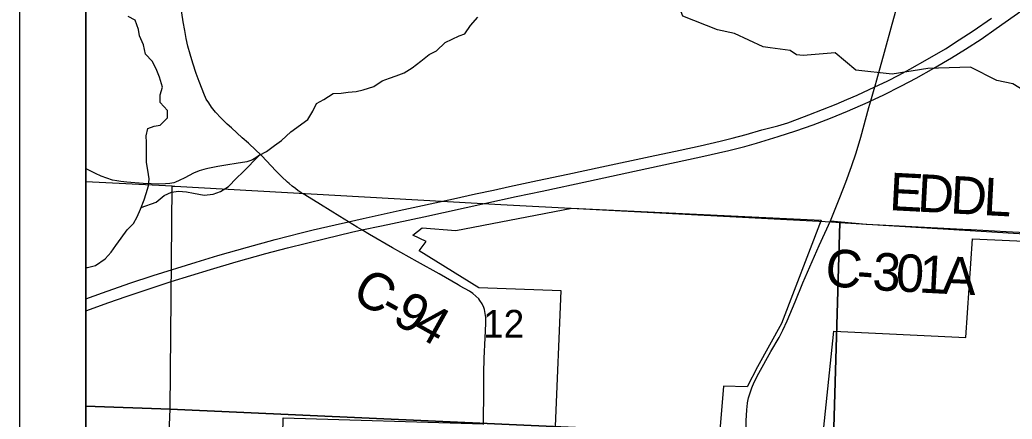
# Model space of a CAD drawing. Extents: x 0 to 34, y 0 to 22.
# Drawn here: x 23.917 to 25.417, y 15.184 to 15.788 of the extents above; entities that cross this region are included whole.
import ezdxf

# ---------------------------------------------------------------- set-up
doc = ezdxf.new("R2010")
doc.units = 0
for name, color, linetype in [('GM_X_Adjacent_County', 7, 'Continuous'), ('GM_X_Corporation', 7, 'Continuous'), ('GM_X_County', 7, 'Continuous'), ('GM_X_County_Road', 7, 'Continuous'), ('GM_X_County_Road_Text', 7, 'Continuous'), ('GM_X_Minor_River', 7, 'Continuous'), ('GM_X_Section', 7, 'Continuous'), ('GM_X_Section_Text', 7, 'Continuous'), ('GM_X_State_Route', 7, 'Continuous'), ('GM_X_Township', 7, 'Continuous'), ('GM_X_Township_Road', 7, 'Continuous'), ('SH_Data', 7, 'Continuous')]:
    doc.layers.add(name, color=color, linetype=linetype)

msp = doc.modelspace()

# ---------------------------------------------------------------- linework, layer by layer
at = {"layer": 'GM_X_Adjacent_County'}
msp.add_lwpolyline([(24.0167, 18.0693), (24.0167, 14.1), (30.8167, 14.1), (30.8167, 17.8174)], dxfattribs=at)
at = {"layer": 'GM_X_Corporation'}
for points in [[(24.7267, 15.1736), (24.7351, 15.3783), (24.6107, 15.383), (24.5203, 15.439), (24.531, 15.4532), (24.5108, 15.4628), (24.5251, 15.4735), (24.5757, 15.4698), (24.7511, 15.5032), (25.1283, 15.4854), (25.0682, 15.3289), (25.0319, 15.2635), (25.0165, 15.2331), (24.9808, 15.2343), (24.9754, 15.1671)], [(25.1307, 15.1576), (25.1474, 15.3176), (25.3472, 15.3081), (25.3574, 15.4568), (25.4692, 15.452)], [(24.3104, 14.9594), (24.3146, 15.1862), (24.6178, 15.1772)]]:
    msp.add_lwpolyline(points, dxfattribs=at)
at = {"layer": 'GM_X_County'}
msp.add_lwpolyline([(24.0167, 18.0693), (24.0167, 14.1), (30.8167, 14.1), (30.8167, 17.8174)], dxfattribs=at)
at = {"layer": 'GM_X_County_Road'}
for points in [[(25.1425, 15.4841), (25.1568, 15.5197), (25.1659, 15.5428), (25.1743, 15.5662), (25.1811, 15.5869), (25.1882, 15.6107), (25.2007, 15.6556), (25.2035, 15.6656), (25.2094, 15.6868), (25.2098, 15.6883), (25.2124, 15.6975), (25.2241, 15.7393), (25.2355, 15.7813), (25.2565, 15.856)], [(24.2806, 15.5843), (24.2736, 15.5913), (24.2622, 15.6017), (24.2529, 15.6099), (24.2369, 15.6247), (24.2302, 15.6304), (24.221, 15.6394), (24.2125, 15.6483), (24.2063, 15.6563), (24.2023, 15.6624), (24.1986, 15.6684), (24.195, 15.6765), (24.1924, 15.6833), (24.1879, 15.6949), (24.1834, 15.7072), (24.1784, 15.7225), (24.1741, 15.7361), (24.1705, 15.7482), (24.1681, 15.7599), (24.1659, 15.7721), (24.1634, 15.7853), (24.1601, 15.8085)], [(24.3384, 15.5293), (24.3376, 15.5298), (24.3333, 15.533), (24.3286, 15.5366), (24.3238, 15.5405), (24.3214, 15.5425), (24.3125, 15.551), (24.3037, 15.56), (24.2824, 15.5825), (24.2806, 15.5843)], [(24.5796, 15.3873), (24.5507, 15.404), (24.5182, 15.4222), (24.4803, 15.4434), (24.4454, 15.4635), (24.4338, 15.4704), (24.4267, 15.4746), (24.4134, 15.4829), (24.4003, 15.491), (24.3711, 15.5088), (24.3475, 15.5234), (24.3449, 15.5251), (24.3423, 15.5267), (24.3399, 15.5282), (24.3384, 15.5293)], [(25.0144, 15.164), (25.0149, 15.1769), (25.0149, 15.1831), (25.0153, 15.1897), (25.0158, 15.1988), (25.0163, 15.2029), (25.0172, 15.2089), (25.0187, 15.2167), (25.0203, 15.2228), (25.0234, 15.2317), (25.0271, 15.2402), (25.0343, 15.2541), (25.0525, 15.2865), (25.0647, 15.3081), (25.0704, 15.3191), (25.0768, 15.3331), (25.0889, 15.3617), (25.1009, 15.3903), (25.1256, 15.4472), (25.1425, 15.4841)], [(25.1425, 15.4841), (25.1963, 15.4794), (25.2462, 15.4767), (25.352, 15.4711)], [(25.352, 15.4711), (25.3554, 15.471), (25.3729, 15.47), (25.4079, 15.4683), (25.4671, 15.4653), (25.5079, 15.4633), (25.6093, 15.4583), (25.6116, 15.4582), (25.6527, 15.4557), (25.6644, 15.4552), (25.6713, 15.4548), (25.68, 15.4547), (25.6869, 15.4545), (25.6993, 15.4549), (25.7007, 15.455), (25.7066, 15.4556), (25.7146, 15.4565), (25.7166, 15.4566), (25.7239, 15.4573), (25.7409, 15.4583), (25.7413, 15.4583)], [(24.6178, 15.1765), (24.618, 15.1862), (24.6184, 15.2203), (24.6183, 15.2545), (24.619, 15.2762), (24.6202, 15.3073), (24.6213, 15.329), (24.6212, 15.3382), (24.6205, 15.3443), (24.6191, 15.3502), (24.6181, 15.3531), (24.6156, 15.3586), (24.6124, 15.3638), (24.6106, 15.3662), (24.6064, 15.3705), (24.6016, 15.3743), (24.5965, 15.3777), (24.5825, 15.3856), (24.5796, 15.3873)]]:
    msp.add_lwpolyline(points, dxfattribs=at)
at = {"layer": 'GM_X_Minor_River'}
for points in [[(25.5761, 15.6015), (25.5645, 15.6263), (25.5549, 15.6385), (25.5447, 15.6449), (25.4905, 15.6515), (25.4773, 15.656), (25.4336, 15.6817), (25.4184, 15.6915), (25.3942, 15.6963), (25.354, 15.7163), (25.2896, 15.7146), (25.2359, 15.706), (25.1806, 15.7119), (25.1494, 15.7384), (25.101, 15.734), (25.0912, 15.7351), (25.0813, 15.7416), (25.0514, 15.7456), (25.0408, 15.7471), (24.9975, 15.7674), (24.9714, 15.773), (24.919, 15.7937), (24.9079, 15.8229)], [(24.0167, 15.4137), (24.0192, 15.4138), (24.031, 15.4165), (24.0457, 15.4268), (24.0548, 15.437), (24.0616, 15.4469), (24.0699, 15.458), (24.079, 15.4705), (24.0884, 15.4801), (24.094, 15.4903), (24.0989, 15.5017), (24.1046, 15.5158), (24.1076, 15.5257), (24.1113, 15.5371), (24.112, 15.5477), (24.1104, 15.5606), (24.1081, 15.5724), (24.1081, 15.5895), (24.1084, 15.6027), (24.1076, 15.6126), (24.1102, 15.624), (24.1197, 15.6271), (24.1291, 15.6286), (24.1397, 15.6401), (24.14, 15.6511), (24.129, 15.6632), (24.1286, 15.6749), (24.1323, 15.6863), (24.1277, 15.7015), (24.1227, 15.714), (24.117, 15.7258), (24.1067, 15.7364), (24.1036, 15.7504), (24.0978, 15.7637), (24.0963, 15.7735), (24.0909, 15.7876), (24.0806, 15.7932)], [(24.5808, 15.7641), (24.5894, 15.7668), (24.5981, 15.7794), (24.6094, 15.7923)], [(24.1, 15.5045), (24.1228, 15.5124), (24.1349, 15.5223), (24.1459, 15.5277), (24.1565, 15.5293), (24.1686, 15.5282), (24.1793, 15.5259), (24.1952, 15.5229), (24.2089, 15.5245), (24.2202, 15.5287), (24.2323, 15.5363), (24.2441, 15.5485), (24.2539, 15.558), (24.2792, 15.5836), (24.2894, 15.5889), (24.3019, 15.5981), (24.3121, 15.6057), (24.3265, 15.619), (24.3522, 15.6373), (24.3597, 15.6499), (24.365, 15.6617), (24.3764, 15.6678), (24.3907, 15.6766), (24.4025, 15.677), (24.4131, 15.6785), (24.4253, 15.6797), (24.4359, 15.6824), (24.4518, 15.6874), (24.4646, 15.6958), (24.4756, 15.7), (24.4859, 15.7035), (24.4976, 15.7081), (24.5097, 15.7157), (24.523, 15.7256), (24.5354, 15.7355), (24.5468, 15.7413), (24.5596, 15.7538), (24.5706, 15.7588), (24.5808, 15.7641)]]:
    msp.add_lwpolyline(points, dxfattribs=at)
at = {"layer": 'GM_X_Section'}
for p, q in [((24.0167, 15.5431), (24.0167, 15.2043)), ((24.0167, 15.2043), (24.0167, 14.2067))]:
    msp.add_line(p, q, dxfattribs=at)
for points in [[(24.0167, 15.2043), (24.144, 15.1997), (24.1468, 15.5367), (24.0167, 15.5431)], [(24.0167, 14.2067), (24.102, 14.2034), (24.144, 15.1997), (24.0167, 15.2043)]]:
    msp.add_lwpolyline(points, dxfattribs=at)
for points in [[(24.1468, 15.5367), (24.151, 15.5365), (24.644, 15.5087), (25.1441, 15.4826), (25.1568, 15.4818), (25.1469, 15.1542), (24.144, 15.1997)], [(25.6327, 15.4525), (26.1658, 15.4276), (26.1585, 15.1031), (25.1469, 15.1542), (25.1568, 15.4818)], [(24.144, 15.1997), (25.1469, 15.1542), (25.1079, 14.1514), (24.102, 14.2034)]]:
    msp.add_lwpolyline(points, close=True, dxfattribs=at)
at = {"layer": 'GM_X_State_Route'}
for points in [[(24.0167, 15.3483), (24.0512, 15.3609), (24.0776, 15.3701), (24.1455, 15.3923), (24.2049, 15.4108), (24.2436, 15.4222), (24.2885, 15.4347), (24.3216, 15.4433), (24.3788, 15.4577), (24.4181, 15.467), (24.4338, 15.4704), (24.4637, 15.4768), (24.5274, 15.4905), (24.6214, 15.511), (24.667, 15.5208), (24.7065, 15.5292), (24.7764, 15.5441), (24.8462, 15.5592), (24.9464, 15.5809), (24.9887, 15.5907), (25.0128, 15.5968), (25.0308, 15.6017), (25.0634, 15.6116), (25.09, 15.6202), (25.1164, 15.6295), (25.1425, 15.6394), (25.1683, 15.6501), (25.1996, 15.6638), (25.2035, 15.6656), (25.2221, 15.6743), (25.2499, 15.6881), (25.2718, 15.6997), (25.2989, 15.7149), (25.3257, 15.7306), (25.3468, 15.7437), (25.3701, 15.759), (25.3931, 15.775), (25.4336, 15.8038)], [(24.0167, 15.3664), (24.0418, 15.3755), (24.0829, 15.3898), (24.1183, 15.4015), (24.1835, 15.4218), (24.2162, 15.4317), (24.2609, 15.4446), (24.3029, 15.456), (24.342, 15.4661), (24.3601, 15.4705), (24.3933, 15.4784), (24.4134, 15.4829), (24.4357, 15.4879), (24.4903, 15.4998), (24.5722, 15.5175), (24.6055, 15.5248), (24.6328, 15.5308), (24.657, 15.5361), (24.6996, 15.5451), (24.7452, 15.5548), (24.7968, 15.5658), (24.8697, 15.5817), (24.9153, 15.5913), (24.9456, 15.5978), (24.9759, 15.6047), (24.994, 15.6092), (25.015, 15.6148), (25.0389, 15.6216), (25.051, 15.6246), (25.0629, 15.628), (25.0778, 15.6326), (25.0925, 15.6377), (25.1099, 15.6444), (25.1513, 15.6604), (25.1672, 15.6675), (25.1828, 15.6742), (25.2094, 15.6868), (25.2152, 15.6895), (25.2292, 15.6961), (25.2458, 15.7046), (25.2623, 15.7135), (25.2894, 15.7286), (25.3162, 15.7444), (25.3373, 15.7576), (25.358, 15.7713), (25.3861, 15.7908)]]:
    msp.add_lwpolyline(points, dxfattribs=at)
at = {"layer": 'GM_X_Township'}
msp.add_lwpolyline([(24.0167, 18.0693), (24.0167, 14.1), (26.1244, 14.1)], dxfattribs=at)
at = {"layer": 'GM_X_Township_Road'}
msp.add_lwpolyline([(24.2806, 15.5843), (24.277, 15.582), (24.2711, 15.5782), (24.2683, 15.5764), (24.2644, 15.5749), (24.2597, 15.5735), (24.2436, 15.5708), (24.2313, 15.5688), (24.216, 15.5662), (24.2008, 15.5631), (24.1949, 15.5619), (24.1877, 15.5598), (24.1792, 15.5562), (24.1663, 15.5493), (24.1578, 15.5453), (24.1521, 15.5429), (24.1493, 15.5419), (24.1463, 15.5411), (24.1433, 15.5406), (24.1371, 15.54), (24.1278, 15.5399), (24.103, 15.5409), (24.0782, 15.5426), (24.0692, 15.5435), (24.0631, 15.5445), (24.057, 15.5459), (24.0481, 15.5487), (24.0394, 15.552), (24.0309, 15.5558), (24.0198, 15.5614), (24.0167, 15.5633)], dxfattribs=at)
at = {"layer": 'SH_Data'}
for points in [[(23.9167, 21), (30.9167, 21), (30.9167, 14), (23.9167, 14)], [(24.0167, 20.9), (30.8167, 20.9), (30.8167, 14.1), (24.0167, 14.1)]]:
    msp.add_lwpolyline(points, close=True, dxfattribs=at)

# ---------------------------------------------------------------- texts
at = {"layer": 'GM_X_County_Road_Text'}
for s, rotation, p in [('E', 357.0073, (25.2305, 15.5005)), ('D', 357.0043, (25.273, 15.4983)), ('D', 357.0079, (25.3229, 15.4956)), ('L', 357.003, (25.3728, 15.493)), ('C', 354.1158, (25.1326, 15.3867)), ('3', 356.5623, (25.2049, 15.3799)), ('0', 356.9932, (25.2403, 15.3778)), ('1', 357.0225, (25.2753, 15.376)), ('A', 357.5211, (25.3108, 15.3741)), ('C', 329.3716, (24.416, 15.3673)), ('-', 355.6814, (25.1807, 15.3818)), ('9', 330.8024, (24.4778, 15.3313)), ('-', 330.791, (24.4575, 15.3427)), ('4', 330.8151, (24.5084, 15.3142))]:
    msp.add_text(s, height=0.0568, rotation=rotation, dxfattribs=at).set_placement(p)
at = {"layer": 'GM_X_Section_Text'}
msp.add_text('12', height=0.04186, rotation=0, dxfattribs=at).set_placement((24.6171, 15.3077))

doc.saveas('drawing.dxf')
